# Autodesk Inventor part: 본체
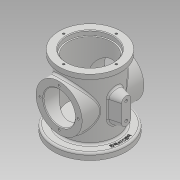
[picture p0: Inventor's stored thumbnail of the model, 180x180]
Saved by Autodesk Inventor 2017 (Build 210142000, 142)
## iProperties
Part Number: 본체
Material: 일반
Document SubType Name: Modeling
Designer: MRC
Density: 1 g/cm^3
Appearance: 기본값
Mass: 316.836 g
Surface Area: 757.291 cm^2
Volume: 316.836 cm^3
Author: MRC
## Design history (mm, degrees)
sketch "스케치2"
  geometry: C1 r 55 at (0, 0); 1 further point
  constraints: 1 centre point, 1 coincident
  dimensions: "d0" = 110 diameter of C1
extrude "돌출1" new body sketch "스케치2" distance "d1" = 10; taper "d2" = 0 deg
sketch "스케치3"
  geometry: C1 r 55 at (0, 0) reference; C2 r 40 at (0, 0)
  constraints: 1 centre point, 1 coincident
  dimensions: "d3" = 80 diameter of C2
extrude "돌출2" join sketch "스케치3" distance "d4" = 88; taper "d5" = 0 deg
sketch "스케치4"
  geometry: C1 r 40 at (0, 0) reference; C2 r 47 at (0, 0)
  constraints: 2 coincident, 1 centre point
  dimensions: "d6" = 94 diameter of C2
extrude "돌출3" join sketch "스케치4" distance "d7" = 10; taper "d8" = 0 deg
sketch "스케치9"
  geometry: L1 (-55, 0)-(55, 0) reference; C1 r 35 at (0, 54); 1 further point
  constraints: 1 centre point
  dimensions: "d21" = 70 diameter of C1; "d22" = 54 distance from line of L1 C1.centre
extrude "돌출8" join sketch "스케치9" stored distance "d23" = 94; taper "d24" = 0 deg
sketch "스케치5"
  geometry: C1 r 55 at (0, 0) reference; C2 r 33 at (0, 0)
  constraints: 1 centre point, 1 coincident
  dimensions: "d9" = 66 diameter of C2
extrude "돌출4" cut sketch "스케치5" distance "d10" = 16; taper "d11" = 0 deg
sketch "스케치6"
  geometry: C1 r 47 at (0, 0) reference; C2 r 33 at (0, 0)
  constraints: 1 centre point, 1 coincident
  dimensions: "d12" = 66 diameter of C2
extrude "돌출5" cut sketch "스케치6" distance "d13" = 86; taper "d14" = 0 deg
sketch "스케치7"
  geometry: C1 r 33 at (0, 0) reference; C2 r 47 at (0, 0) reference; C3 r 35 at (0, 0)
  constraints: 1 centre point, 1 coincident
  dimensions: "d15" = 70 diameter of C3
extrude "돌출6" cut sketch "스케치7" distance "d16" = 7; taper "d17" = 0 deg
sketch "스케치8"
  geometry: C1 r 33 at (0, 0) reference; C2 r 5 at (0, 0)
  constraints: 1 centre point, 1 coincident
  dimensions: "d18" = 10 diameter of C2
extrude "돌출7" cut sketch "스케치8" distance "d19" = 30; taper "d20" = 0 deg
sketch "스케치10"
  geometry: C1 r 35 at (0, 0) reference; C2 r 24 at (0, 0); 1 further point
  constraints: 1 centre point, 1 coincident
  dimensions: "d25" = 48 diameter of C2
extrude "돌출9" cut sketch "스케치10" distance "d26" = 94; taper "d27" = 0 deg
chamfer "모따기1" distance "d28" = 1; stored, may be unused: second distance "d29" = 2, angle "d30" = 45 deg
fillet "모깎기1" dims "d32" = 3
sketch "스케치11"
  geometry: C1 r 43 at (0, 0) reference; C2 r 50 at (0, 0)
  constraints: 1 centre point, 1 coincident, 1 other
  dimensions: "d33" = 100 diameter of C2
feature "엠보싱1" sketch "스케치11" dims "d34" = 0.5, "d35" = 0
sketch "스케치12" dims "d36" = 58
  geometry: C1 r 35 at (0, 0) reference; C2 r 25 at (0, 0) reference; 3 further points
  constraints: 2 vertical alignment, 1 coincident, 2 other
hole "구멍1" sketch "스케치12" at (0, 29) diameter "d37" = 3.242; stored, may be unused: countersink angle "d41" = 90 deg, drill point angle "d43" = 118 deg; dims "d38" = 6, "d39" = 4, "d40" = 6, "d42" = 8
sketch "스케치13" dims "d47" = 80
  geometry: C1 r 47 at (0, 0) reference; C2 r 36 at (0, 0) reference; 2 further points
  constraints: 2 horizontal alignment, 1 coincident, 2 other
hole "구멍2" sketch "스케치13" at (40, 0) diameter "d48" = 3.242; stored, may be unused: countersink angle "d52" = 90 deg, drill point angle "d54" = 118 deg; dims "d49" = 6, "d50" = 4, "d51" = 6, "d53" = 8
sketch "스케치14" dims "d58" = 58
  geometry: C1 r 35 at (0, 0) reference; C2 r 25 at (0, 0) reference; 3 further points
  constraints: 2 horizontal alignment, 1 coincident, 2 other
hole "구멍3" sketch "스케치14" at (-29, 0) diameter "d59" = 3.242; stored, may be unused: countersink angle "d63" = 90 deg, drill point angle "d65" = 118 deg; dims "d60" = 6, "d61" = 4, "d62" = 6, "d64" = 8
node "작업 평면1"
sketch "스케치15"
  geometry: L1 (0, 74)-(0, 34); L2 (-7, 67)-(-7, 41); L3 (7, 41)-(7, 67); L4 (-55, 0)-(55, 0) reference; A1 r 7 centre (0, 67) between (7, 67) and (-7, 67); A2 r 7 centre (0, 41) between (-7, 41) and (7, 41); 3 further points
  constraints: 8 end point, 6 point on circle, 4 tangent, 2 centre point, 2 midpoint, 2 point on line, 1 parallel, 1 vertical, 1 vertical alignment
  dimensions: "d69" = 54 distance from line of L4 point (0, 54); "d70" = 7 radius of A1; "d71" = 40 distance of L1.end L1.start
extrude "돌출10" join sketch "스케치15" stored distance "d72" = 94; taper "d73" = 15 deg
sketch "스케치16"
  geometry: A1 r 7 centre (-41, 0) between (-41, -7) and (-41, 7) reference; A2 r 7 centre (-67, 0) between (-67, 7) and (-67, -7) reference; 3 further points
  constraints: 2 coincident
hole "구멍4" sketch "스케치16" at (-41, 0), (-67, 0) diameter "d74" = 4.134; stored, may be unused: countersink angle "d78" = 90 deg, drill point angle "d80" = 118 deg; dims "d75" = 6, "d76" = 4, "d77" = 6, "d79" = 8
fillet "모깎기2" dims "d81" = 3
node "솔리드1"
pattern_circular "원형 패턴1" dims angle "d45" = 360 deg
pattern_circular "원형 패턴2" dims angle "d56" = 360 deg
pattern_circular "원형 패턴3" dims angle "d67" = 360 deg
other parameters: "d31" = 55
